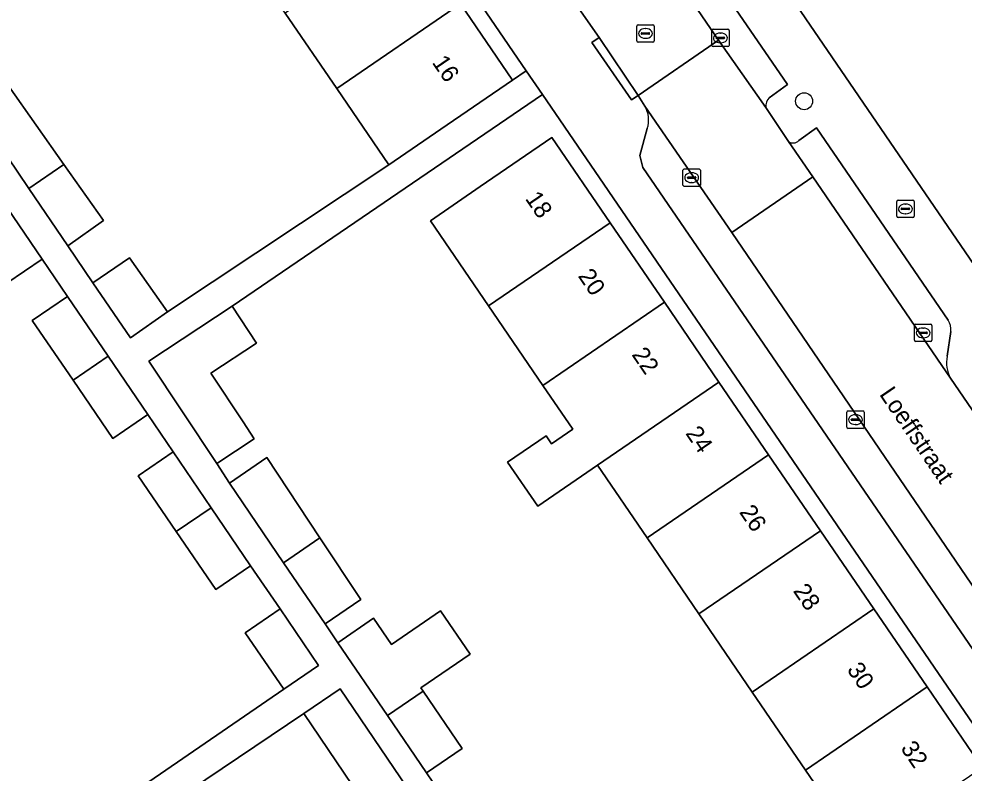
# Model space of a CAD drawing. Extents: x 157445 to 158888, y 383061 to 384688.
# Drawn here: x 158256.9 to 158311.3, y 383511.9 to 383555.3 of the extents above; entities that cross this region are included whole.
import ezdxf

# ---------------------------------------------------------------- set-up
doc = ezdxf.new("R2010")
doc.units = 0
for name, color, linetype in [('IMGEO_Boom', 7, 'Continuous'), ('IMGEO_Brandkraan', 7, 'Continuous'), ('IMGEO_Erf', 7, 'Continuous'), ('IMGEO_Kolk', 7, 'Continuous'), ('IMGEO_Openbare_ruimte_label', 7, 'Continuous'), ('IMGEO_Pand', 7, 'Continuous'), ('IMGEO_Pand_nummerreeks', 7, 'Continuous'), ('IMGEO_Parkeervlak_open', 7, 'Continuous'), ('IMGEO_Rijbaan_lokaal_open', 7, 'Continuous'), ('IMGEO_Rioolput', 7, 'Continuous'), ('IMGEO_Voetpad_open', 7, 'Continuous')]:
    doc.layers.add(name, color=color, linetype=linetype)

msp = doc.modelspace()

# ---------------------------------------------------------------- linework, layer by layer
at = {"layer": 'IMGEO_Boom'}
msp.add_circle((158302.088, 383550.528), 0.489, dxfattribs=at)
at = {"layer": 'IMGEO_Brandkraan'}
for p, q in [((158307.414, 383543.907), (158307.414, 383544.759)), ((158307.489, 383544.833), (158308.341, 383544.833)), ((158308.415, 383544.759), (158308.415, 383543.907)), ((158307.673, 383544.327), (158307.673, 383544.339)), ((158308.111, 383544.29), (158307.713, 383544.29)), ((158307.716, 383544.376), (158308.114, 383544.376)), ((158307.902, 383544.613), (158307.927, 383544.613)), ((158308.157, 383544.339), (158308.157, 383544.327)), ((158308.341, 383543.833), (158307.489, 383543.833)), ((158307.925, 383544.053), (158307.9, 383544.053))]:
    msp.add_line(p, q, dxfattribs=at)
for points in [[(158307.414, 383543.907), (158307.414, 383544.759)], [(158307.489, 383544.833), (158308.341, 383544.833)], [(158308.415, 383544.759), (158308.415, 383543.907)], [(158308.341, 383543.833), (158307.489, 383543.833)]]:
    msp.add_lwpolyline(points, dxfattribs=at)
for centre, radius, start, end in [((158307.491, 383544.757), 0.0765, 91.552, 178.448), ((158307.491, 383544.757), 0.0765, 91.552, 178.448), ((158308.339, 383544.757), 0.0765, 1.552, 88.448), ((158308.339, 383544.757), 0.0765, 1.552, 88.448), ((158307.713, 383544.336), 0.0403, 85.8775, 175.7526), ((158307.71, 383544.326), 0.0366, 178.938, 274.7102), ((158308.114, 383544.333), 0.043, 264.8664, 352.4533), ((158308.118, 383544.338), 0.0386, 1.7309, 96.639), ((158307.491, 383543.909), 0.0765, 181.552, 268.448), ((158307.491, 383543.909), 0.0765, 181.552, 268.448), ((158308.339, 383543.909), 0.0765, 271.552, 358.448), ((158308.339, 383543.909), 0.0765, 271.552, 358.448)]:
    msp.add_arc(centre, radius, start, end, dxfattribs=at)
for centre, major_axis, ratio, start_param, end_param in [((158307.901, 383544.333), (-0.387, 0.002), 0.722429, 4.712389, 7.853982), ((158307.926, 383544.333), (-0.39, 0.002), 0.717154, 1.570796, 4.712389)]:
    msp.add_ellipse(centre, major_axis=major_axis, ratio=ratio, start_param=start_param, end_param=end_param, dxfattribs=at)
at = {"layer": 'IMGEO_Erf'}
for points in [[(158322.051, 383583.576), (158306.438, 383606.562), (158284.721, 383591.707), (158280.579, 383588.831), (158280.654, 383586.674), (158297.815, 383561.626), (158297.69, 383561.544), (158301.237, 383556.346), (158301.401, 383556.432), (158316.985, 383533.617)], [(158256.313, 383551.418), (158259.498, 383546.89), (158261.771, 383543.66), (158259.723, 383542.219), (158261.171, 383540.091), (158263.271, 383541.527), (158265.465, 383538.411), (158278.195, 383546.876), (158275.199, 383551.26), (158272.237, 383555.595), (158269.115, 383560.163), (158265.897, 383564.872), (158262.909, 383569.245), (158259.856, 383573.712), (158256.815, 383578.162)], [(158313.103, 383512.83), (158287.042, 383550.909), (158269.172, 383538.744), (158270.58, 383536.62), (158267.959, 383534.883), (158269.808, 383532.093), (158270.453, 383531.12), (158268.293, 383529.688), (158269.033, 383528.571), (158271.173, 383530.033), (158274.228, 383525.423), (158276.58, 383521.874), (158274.526, 383520.47), (158275.263, 383519.387), (158277.317, 383520.791), (158278.343, 383519.283), (158281.174, 383521.217), (158282.878, 383518.722), (158280.043, 383516.785), (158280.166, 383516.604), (158282.41, 383513.308), (158280.356, 383511.905), (158281.822, 383509.753)], [(158305.332, 383507.439), (158302.171, 383512.064), (158299.103, 383516.553), (158296.036, 383521.042), (158293.05, 383525.411), (158290.193, 383529.591), (158286.757, 383527.243), (158285.029, 383529.772), (158287.238, 383531.283), (158287.547, 383530.831), (158288.773, 383531.67), (158287.053, 383534.187), (158283.933, 383538.753), (158280.582, 383543.656), (158283.45, 383545.616), (158287.578, 383548.437), (158290.929, 383543.534), (158294.049, 383538.968), (158297.19, 383534.373), (158300.046, 383530.193), (158303.032, 383525.823), (158306.099, 383521.336), (158309.168, 383516.846), (158312.329, 383512.22)], [(158255.504, 383511.877), (158258.57, 383507.409), (158272.143, 383516.718), (158269.935, 383519.955), (158271.935, 383521.327), (158270.24, 383523.818), (158268.237, 383522.444), (158265.965, 383525.775), (158263.78, 383528.978), (158265.79, 383530.356), (158264.328, 383532.504), (158262.316, 383531.124), (158260.025, 383534.483), (158257.682, 383537.917), (158259.701, 383539.303), (158258.239, 383541.451), (158256.218, 383540.064)]]:
    msp.add_lwpolyline(points, dxfattribs=at)
for points in [[(158261.412, 383588.358), (158260.646, 383587.833), (158263.932, 383583.024), (158266.973, 383578.575), (158270.026, 383574.107), (158273.013, 383569.736), (158276.233, 383565.025), (158279.354, 383560.458), (158282.316, 383556.124), (158285.312, 383551.74), (158286.103, 383552.281)], [(158286.652, 383500.11), (158285.192, 383502.264), (158283.11, 383500.837), (158280.867, 383504.146), (158277.943, 383508.46), (158273.296, 383515.317), (158248.726, 383498.787), (158261.869, 383479.658), (158263.225, 383478.825), (158267.616, 383481.822), (158264.437, 383486.465), (158261.443, 383490.837), (158258.5, 383495.134), (158255.168, 383500), (158255.099, 383500.101), (158259.224, 383502.926), (158262.19, 383504.957), (158265.591, 383499.994), (158268.536, 383495.697), (158271.532, 383491.325), (158274.714, 383486.682), (158287.155, 383494.87), (158284.57, 383498.683)]]:
    msp.add_lwpolyline(points, close=True, dxfattribs=at)
at = {"layer": 'IMGEO_Kolk'}
for p, q in [((158296.77, 383553.739), (158296.77, 383554.591)), ((158296.845, 383554.665), (158297.697, 383554.665)), ((158297.258, 383554.445), (158297.283, 383554.445)), ((158297.771, 383554.591), (158297.771, 383553.739)), ((158297.029, 383554.159), (158297.029, 383554.171)), ((158297.467, 383554.122), (158297.069, 383554.122)), ((158297.072, 383554.208), (158297.47, 383554.208)), ((158297.281, 383553.885), (158297.256, 383553.885)), ((158297.513, 383554.171), (158297.513, 383554.159)), ((158297.697, 383553.665), (158296.845, 383553.665)), ((158295.117, 383545.704), (158295.117, 383546.556)), ((158295.192, 383546.63), (158296.044, 383546.63)), ((158295.605, 383546.41), (158295.63, 383546.41)), ((158296.118, 383546.556), (158296.118, 383545.704)), ((158295.376, 383546.124), (158295.376, 383546.136)), ((158295.814, 383546.087), (158295.416, 383546.087)), ((158295.419, 383546.173), (158295.817, 383546.173)), ((158295.628, 383545.85), (158295.603, 383545.85)), ((158295.86, 383546.136), (158295.86, 383546.124)), ((158296.044, 383545.63), (158295.192, 383545.63)), ((158308.435, 383536.778), (158308.435, 383537.63)), ((158308.51, 383537.704), (158309.362, 383537.704)), ((158309.436, 383537.63), (158309.436, 383536.778)), ((158308.694, 383537.198), (158308.694, 383537.21)), ((158309.132, 383537.161), (158308.734, 383537.161)), ((158308.737, 383537.247), (158309.135, 383537.247)), ((158308.923, 383537.484), (158308.948, 383537.484)), ((158309.178, 383537.21), (158309.178, 383537.198)), ((158309.362, 383536.704), (158308.51, 383536.704)), ((158308.946, 383536.924), (158308.921, 383536.924)), ((158304.616, 383532.715), (158305.468, 383532.715)), ((158304.541, 383531.789), (158304.541, 383532.641)), ((158304.8, 383532.209), (158304.8, 383532.221)), ((158305.238, 383532.172), (158304.84, 383532.172)), ((158304.843, 383532.258), (158305.241, 383532.258)), ((158305.029, 383532.495), (158305.054, 383532.495)), ((158305.284, 383532.221), (158305.284, 383532.209)), ((158305.542, 383532.641), (158305.542, 383531.789)), ((158305.468, 383531.715), (158304.616, 383531.715)), ((158305.052, 383531.935), (158305.027, 383531.935))]:
    msp.add_line(p, q, dxfattribs=at)
for points in [[(158296.77, 383553.739), (158296.77, 383554.591)], [(158296.845, 383554.665), (158297.697, 383554.665)], [(158297.771, 383554.591), (158297.771, 383553.739)], [(158297.697, 383553.665), (158296.845, 383553.665)], [(158295.117, 383545.704), (158295.117, 383546.556)], [(158295.192, 383546.63), (158296.044, 383546.63)], [(158296.118, 383546.556), (158296.118, 383545.704)], [(158296.044, 383545.63), (158295.192, 383545.63)], [(158308.435, 383536.778), (158308.435, 383537.63)], [(158308.51, 383537.704), (158309.362, 383537.704)], [(158309.436, 383537.63), (158309.436, 383536.778)], [(158309.362, 383536.704), (158308.51, 383536.704)], [(158304.616, 383532.715), (158305.468, 383532.715)], [(158304.541, 383531.789), (158304.541, 383532.641)], [(158305.542, 383532.641), (158305.542, 383531.789)], [(158305.468, 383531.715), (158304.616, 383531.715)]]:
    msp.add_lwpolyline(points, dxfattribs=at)
for centre, radius, start, end in [((158296.847, 383554.589), 0.0765, 91.552, 178.448), ((158296.847, 383554.589), 0.0765, 91.552, 178.448), ((158297.695, 383554.589), 0.0765, 1.552, 88.448), ((158297.695, 383554.589), 0.0765, 1.552, 88.448), ((158297.069, 383554.168), 0.0403, 85.8775, 175.7526), ((158297.066, 383554.158), 0.0366, 178.938, 274.7102), ((158297.47, 383554.165), 0.043, 264.8664, 352.4533), ((158297.474, 383554.17), 0.0386, 1.7309, 96.639), ((158296.847, 383553.741), 0.0765, 181.552, 268.448), ((158296.847, 383553.741), 0.0765, 181.552, 268.448), ((158297.695, 383553.741), 0.0765, 271.552, 358.448), ((158297.695, 383553.741), 0.0765, 271.552, 358.448), ((158295.194, 383546.554), 0.0765, 91.552, 178.448), ((158295.194, 383546.554), 0.0765, 91.552, 178.448), ((158296.042, 383546.554), 0.0765, 1.552, 88.448), ((158296.042, 383546.554), 0.0765, 1.552, 88.448), ((158295.416, 383546.133), 0.0403, 85.8775, 175.7526), ((158295.413, 383546.123), 0.0366, 178.938, 274.7102), ((158295.817, 383546.13), 0.043, 264.8664, 352.4533), ((158295.821, 383546.135), 0.0386, 1.7309, 96.639), ((158295.194, 383545.706), 0.0765, 181.552, 268.448), ((158295.194, 383545.706), 0.0765, 181.552, 268.448), ((158296.042, 383545.706), 0.0765, 271.552, 358.448), ((158296.042, 383545.706), 0.0765, 271.552, 358.448), ((158308.512, 383537.628), 0.0765, 91.552, 178.448), ((158308.512, 383537.628), 0.0765, 91.552, 178.448), ((158309.36, 383537.628), 0.0765, 1.552, 88.448), ((158309.36, 383537.628), 0.0765, 1.552, 88.448), ((158308.734, 383537.207), 0.0403, 85.8775, 175.7526), ((158308.731, 383537.197), 0.0366, 178.938, 274.7102), ((158309.135, 383537.204), 0.043, 264.8664, 352.4533), ((158309.139, 383537.209), 0.0386, 1.7309, 96.639), ((158308.512, 383536.78), 0.0765, 181.552, 268.448), ((158308.512, 383536.78), 0.0765, 181.552, 268.448), ((158309.36, 383536.78), 0.0765, 271.552, 358.448), ((158309.36, 383536.78), 0.0765, 271.552, 358.448), ((158304.618, 383532.639), 0.0765, 91.552, 178.448), ((158304.618, 383532.639), 0.0765, 91.552, 178.448), ((158305.466, 383532.639), 0.0765, 1.552, 88.448), ((158305.466, 383532.639), 0.0765, 1.552, 88.448), ((158304.84, 383532.218), 0.0403, 85.8775, 175.7526), ((158304.837, 383532.208), 0.0366, 178.938, 274.7102), ((158305.241, 383532.215), 0.043, 264.8664, 352.4533), ((158305.245, 383532.22), 0.0386, 1.7309, 96.639), ((158304.618, 383531.791), 0.0765, 181.552, 268.448), ((158304.618, 383531.791), 0.0765, 181.552, 268.448), ((158305.466, 383531.791), 0.0765, 271.552, 358.448), ((158305.466, 383531.791), 0.0765, 271.552, 358.448)]:
    msp.add_arc(centre, radius, start, end, dxfattribs=at)
for centre, major_axis, ratio, start_param, end_param in [((158297.257, 383554.165), (-0.387, 0.002), 0.722429, 4.712389, 7.853982), ((158297.282, 383554.165), (-0.39, 0.002), 0.717154, 1.570796, 4.712389), ((158295.604, 383546.13), (-0.387, 0.002), 0.722429, 4.712389, 7.853982), ((158295.629, 383546.13), (-0.39, 0.002), 0.717154, 1.570796, 4.712389), ((158308.922, 383537.204), (-0.387, 0.002), 0.722429, 4.712389, 7.853982), ((158308.947, 383537.204), (-0.39, 0.002), 0.717154, 1.570796, 4.712389), ((158305.028, 383532.215), (-0.387, 0.002), 0.722429, 4.712389, 7.853982), ((158305.053, 383532.215), (-0.39, 0.002), 0.717154, 1.570796, 4.712389)]:
    msp.add_ellipse(centre, major_axis=major_axis, ratio=ratio, start_param=start_param, end_param=end_param, dxfattribs=at)
at = {"layer": 'IMGEO_Pand'}
for points in [[(158272.237, 383555.595), (158275.199, 383551.26), (158282.316, 383556.124), (158279.354, 383560.458)], [(158282.316, 383556.124), (158275.199, 383551.26), (158278.195, 383546.876), (158281.184, 383548.919), (158285.312, 383551.74)], [(158254.367, 383550.089), (158257.481, 383545.513), (158259.498, 383546.89), (158256.313, 383551.418)], [(158290.929, 383543.534), (158287.578, 383548.437), (158283.45, 383545.616), (158280.582, 383543.656), (158283.933, 383538.753)], [(158259.498, 383546.89), (158257.481, 383545.513), (158259.723, 383542.219), (158261.771, 383543.66)], [(158255.88, 383544.918), (158253.854, 383543.529), (158256.218, 383540.064), (158258.239, 383541.451)], [(158294.049, 383538.968), (158290.929, 383543.534), (158283.933, 383538.753), (158287.053, 383534.187)], [(158261.171, 383540.091), (158263.335, 383536.912), (158265.465, 383538.411), (158263.271, 383541.527)], [(158259.701, 383539.303), (158257.682, 383537.917), (158260.025, 383534.483), (158262.041, 383535.865)], [(158267.959, 383534.883), (158270.58, 383536.62), (158269.172, 383538.744), (158264.391, 383535.575), (158268.293, 383529.688), (158270.453, 383531.12), (158269.808, 383532.093)], [(158294.049, 383538.968), (158287.053, 383534.187), (158288.773, 383531.67), (158287.547, 383530.831), (158287.238, 383531.283), (158285.029, 383529.772), (158286.757, 383527.243), (158290.193, 383529.591), (158297.19, 383534.373)], [(158262.041, 383535.865), (158260.025, 383534.483), (158262.316, 383531.124), (158264.328, 383532.504)], [(158290.193, 383529.591), (158293.05, 383525.411), (158300.046, 383530.193), (158297.19, 383534.373)], [(158265.79, 383530.356), (158263.78, 383528.978), (158265.965, 383525.775), (158267.971, 383527.152)], [(158269.033, 383528.571), (158272.131, 383523.989), (158274.228, 383525.423), (158271.173, 383530.033)], [(158303.032, 383525.823), (158300.046, 383530.193), (158293.05, 383525.411), (158296.036, 383521.042)], [(158267.971, 383527.152), (158265.965, 383525.775), (158268.237, 383522.444), (158270.24, 383523.818)], [(158299.103, 383516.553), (158306.099, 383521.336), (158303.032, 383525.823), (158296.036, 383521.042)], [(158274.228, 383525.423), (158272.131, 383523.989), (158274.526, 383520.47), (158276.58, 383521.874)], [(158271.935, 383521.327), (158269.935, 383519.955), (158272.143, 383516.718), (158274.145, 383518.081)], [(158302.171, 383512.064), (158309.168, 383516.846), (158306.099, 383521.336), (158299.103, 383516.553)], [(158275.263, 383519.387), (158278.112, 383515.201), (158280.166, 383516.604), (158280.043, 383516.785), (158282.878, 383518.722), (158281.174, 383521.217), (158278.343, 383519.283), (158277.317, 383520.791)], [(158273.296, 383515.317), (158277.943, 383508.46), (158280.026, 383509.887), (158275.386, 383516.733)], [(158280.166, 383516.604), (158278.112, 383515.201), (158280.356, 383511.905), (158282.41, 383513.308)], [(158302.171, 383512.064), (158305.332, 383507.439), (158308.201, 383509.4), (158312.329, 383512.22), (158309.168, 383516.846)]]:
    msp.add_lwpolyline(points, close=True, dxfattribs=at)
at = {"layer": 'IMGEO_Parkeervlak_open'}
for points in [[(158281.287, 383577.232), (158297.166, 383554.041), (158299.891, 383550.174)], [(158300.074, 383550.728), (158301.138, 383551.491), (158293.884, 383562.049), (158293.552, 383561.819)], [(158297.921, 383542.978), (158292.914, 383550.25)], [(158310.383, 383537.936), (158302.808, 383548.999), (158301.792, 383548.262)], [(158293.059, 383548.952), (158292.643, 383547.407)], [(158301.18, 383548.218), (158302.597, 383546.178)], [(158292.643, 383547.407), (158292.804, 383546.711)], [(158292.804, 383546.711), (158313.727, 383516.189)], [(158302.597, 383546.178), (158310.512, 383534.601)], [(158317.262, 383514.634), (158297.921, 383542.978)], [(158310.321, 383535.858), (158310.531, 383537.29)]]:
    msp.add_lwpolyline(points, dxfattribs=at)
for centre, radius, start, end in [((158300.51, 383550.277), 0.627, 134.0128, 189.4279), ((158291.633, 383549.45), 1.51, 340.7559, 31.9923), ((158301.461, 383548.586), 0.463, 232.5982, 315.6262), ((158309.48, 383537.389), 1.055, 354.6061, 31.2017), ((158312.149, 383535.493), 1.864, 168.7044, 208.5755)]:
    msp.add_arc(centre, radius, start, end, dxfattribs=at)
at = {"layer": 'IMGEO_Rijbaan_lokaal_open'}
for points in [[(158276.368, 383584.356), (158274.995, 383586.467), (158270.806, 383592.574), (158267.986, 383596.629), (158259.75, 383608.744), (158255.078, 383605.443), (158256.84, 383602.832), (158258.908, 383599.874), (158259.046, 383599.735), (158261, 383596.831), (158262.585, 383594.528), (158263.501, 383593.197), (158264.184, 383592.177), (158288.053, 383557.407), (158290.293, 383554.184), (158292.53, 383550.856), (158297.166, 383554.041), (158281.287, 383577.232)], [(158297.921, 383542.978), (158302.597, 383546.178), (158301.18, 383548.218), (158299.891, 383550.174), (158297.166, 383554.041), (158292.53, 383550.856), (158292.914, 383550.25)], [(158329.21, 383504.517), (158330.503, 383505.287), (158330.4, 383505.47), (158321.589, 383518.398), (158318.603, 383522.768), (158310.512, 383534.601), (158302.597, 383546.178), (158297.921, 383542.978), (158317.262, 383514.634), (158317.755, 383513.875), (158319.706, 383510.41), (158324.601, 383501.77)]]:
    msp.add_lwpolyline(points, close=True, dxfattribs=at)
at = {"layer": 'IMGEO_Rioolput'}
for p, q in [((158292.456, 383553.996), (158292.456, 383554.848)), ((158292.531, 383554.922), (158293.383, 383554.922)), ((158292.715, 383554.416), (158292.715, 383554.428)), ((158292.758, 383554.465), (158293.156, 383554.465)), ((158292.944, 383554.702), (158292.969, 383554.702)), ((158293.199, 383554.428), (158293.199, 383554.416)), ((158293.457, 383554.848), (158293.457, 383553.996)), ((158293.383, 383553.922), (158292.531, 383553.922)), ((158293.153, 383554.379), (158292.755, 383554.379)), ((158292.967, 383554.142), (158292.942, 383554.142))]:
    msp.add_line(p, q, dxfattribs=at)
for points in [[(158292.456, 383553.996), (158292.456, 383554.848)], [(158292.531, 383554.922), (158293.383, 383554.922)], [(158293.457, 383554.848), (158293.457, 383553.996)], [(158293.383, 383553.922), (158292.531, 383553.922)]]:
    msp.add_lwpolyline(points, dxfattribs=at)
for centre, radius, start, end in [((158292.533, 383554.846), 0.0765, 91.552, 178.448), ((158292.533, 383554.846), 0.0765, 91.552, 178.448), ((158292.755, 383554.425), 0.0403, 85.8775, 175.7526), ((158293.16, 383554.427), 0.0386, 1.7309, 96.639), ((158293.381, 383554.846), 0.0765, 1.552, 88.448), ((158293.381, 383554.846), 0.0765, 1.552, 88.448), ((158292.533, 383553.998), 0.0765, 181.552, 268.448), ((158292.533, 383553.998), 0.0765, 181.552, 268.448), ((158292.752, 383554.415), 0.0366, 178.938, 274.7102), ((158293.156, 383554.422), 0.043, 264.8664, 352.4533), ((158293.381, 383553.998), 0.0765, 271.552, 358.448), ((158293.381, 383553.998), 0.0765, 271.552, 358.448)]:
    msp.add_arc(centre, radius, start, end, dxfattribs=at)
for centre, major_axis, ratio, start_param, end_param in [((158292.943, 383554.422), (-0.387, 0.002), 0.722429, 4.712389, 7.853982), ((158292.968, 383554.422), (-0.39, 0.002), 0.717154, 1.570796, 4.712389)]:
    msp.add_ellipse(centre, major_axis=major_axis, ratio=ratio, start_param=start_param, end_param=end_param, dxfattribs=at)
at = {"layer": 'IMGEO_Voetpad_open'}
for points in [[(158246.999, 383617.179), (158244.36, 383621.051), (158243.465, 383620.474), (158236.284, 383630.945), (158234.717, 383625.799), (158237.929, 383620.937), (158241.491, 383615.546), (158253.203, 383598.26), (158253.341, 383598.153), (158256.385, 383593.609), (158256.493, 383593.672), (158259.462, 383589.365), (158259.632, 383589.105), (158260.521, 383587.747), (158260.646, 383587.833), (158261.412, 383588.358), (158286.103, 383552.281), (158287.042, 383550.909), (158313.103, 383512.83)], [(158293.552, 383561.819), (158293.884, 383562.049), (158301.138, 383551.491), (158300.074, 383550.728)], [(158292.914, 383550.25), (158292.53, 383550.856), (158292.163, 383550.61), (158289.88, 383553.911), (158290.293, 383554.184), (158288.053, 383557.407)], [(158333.845, 383508.772), (158325.365, 383521.154), (158322.136, 383525.869), (158322.372, 383525.976), (158320.263, 383529.073), (158322.521, 383530.674), (158321.142, 383532.711), (158318.872, 383531.117), (158318.38, 383531.84), (158317.112, 383533.721), (158316.985, 383533.617), (158301.401, 383556.432)], [(158281.822, 383509.753), (158280.356, 383511.905), (158278.112, 383515.201), (158275.263, 383519.387), (158274.526, 383520.47), (158272.131, 383523.989), (158269.033, 383528.571), (158268.293, 383529.688), (158264.391, 383535.575), (158269.172, 383538.744), (158287.042, 383550.909), (158286.103, 383552.281), (158285.312, 383551.74), (158281.184, 383548.919), (158278.195, 383546.876), (158265.465, 383538.411), (158263.335, 383536.912), (158261.171, 383540.091), (158259.723, 383542.219), (158257.481, 383545.513), (158254.367, 383550.089)], [(158299.891, 383550.174), (158301.18, 383548.218)], [(158301.792, 383548.262), (158302.808, 383548.999), (158310.383, 383537.936)], [(158313.727, 383516.189), (158292.804, 383546.711), (158292.643, 383547.407), (158293.059, 383548.952)], [(158255.88, 383544.918), (158258.239, 383541.451), (158259.701, 383539.303), (158262.041, 383535.865), (158264.328, 383532.504), (158265.79, 383530.356), (158267.971, 383527.152), (158270.24, 383523.818), (158271.935, 383521.327), (158274.145, 383518.081), (158272.143, 383516.718), (158258.57, 383507.409), (158255.684, 383505.429)], [(158310.531, 383537.29), (158310.321, 383535.858)], [(158310.512, 383534.601), (158318.603, 383522.768), (158321.589, 383518.398)], [(158248.726, 383498.787), (158273.296, 383515.317), (158275.386, 383516.733), (158280.026, 383509.887), (158282.95, 383505.573), (158285.192, 383502.264), (158286.652, 383500.11), (158286.766, 383499.942), (158289.243, 383496.286), (158287.155, 383494.87), (158274.714, 383486.682), (158271.742, 383484.647), (158267.616, 383481.822), (158263.225, 383478.825), (158264.125, 383477.532), (158264.491, 383477.795), (158270.373, 383481.674), (158277.76, 383486.673), (158282.605, 383489.969), (158304.815, 383505.407), (158310.753, 383509.472), (158313.131, 383511.049)]]:
    msp.add_lwpolyline(points, dxfattribs=at)
msp.add_lwpolyline([(158290.293, 383554.184), (158289.88, 383553.911), (158292.163, 383550.61), (158292.53, 383550.856)], close=True, dxfattribs=at)
for centre, radius, start, end in [((158300.51, 383550.277), 0.627, 134.0128, 189.4279), ((158291.633, 383549.45), 1.51, 340.7559, 31.9923), ((158301.461, 383548.586), 0.463, 232.5982, 315.6262), ((158309.48, 383537.389), 1.055, 354.6061, 31.2017), ((158312.149, 383535.493), 1.864, 168.7044, 208.5755)]:
    msp.add_arc(centre, radius, start, end, dxfattribs=at)

# ---------------------------------------------------------------- texts
at = {"layer": 'IMGEO_Openbare_ruimte_label'}
msp.add_text('Loeffstraat', height=1, rotation=304.3256, dxfattribs=at).set_placement((158306.385, 383533.671))
at = {"layer": 'IMGEO_Pand_nummerreeks'}
for s, rotation, p in [('16', 304.3487, (158280.648, 383552.753)), ('18', 304.349, (158286.004, 383544.927)), ('20', 304.349, (158289.047, 383540.475)), ('22', 304.349, (158292.137, 383535.953)), ('24', 304.349, (158295.232, 383531.424)), ('26', 304.349, (158298.326, 383526.897)), ('28', 304.349, (158301.422, 383522.367)), ('30', 304.349, (158304.516, 383517.839)), ('32', 304.349, (158307.607, 383513.317))]:
    msp.add_text(s, height=1, rotation=rotation, dxfattribs=at).set_placement(p)

doc.saveas('drawing.dxf')
